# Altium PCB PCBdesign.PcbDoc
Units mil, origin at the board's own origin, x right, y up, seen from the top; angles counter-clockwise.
Board outline 6000 x 4000 mil, 2 copper layers (Top Layer, Bottom Layer); 43 components, 39 nets, 166 pads, 16 vias.
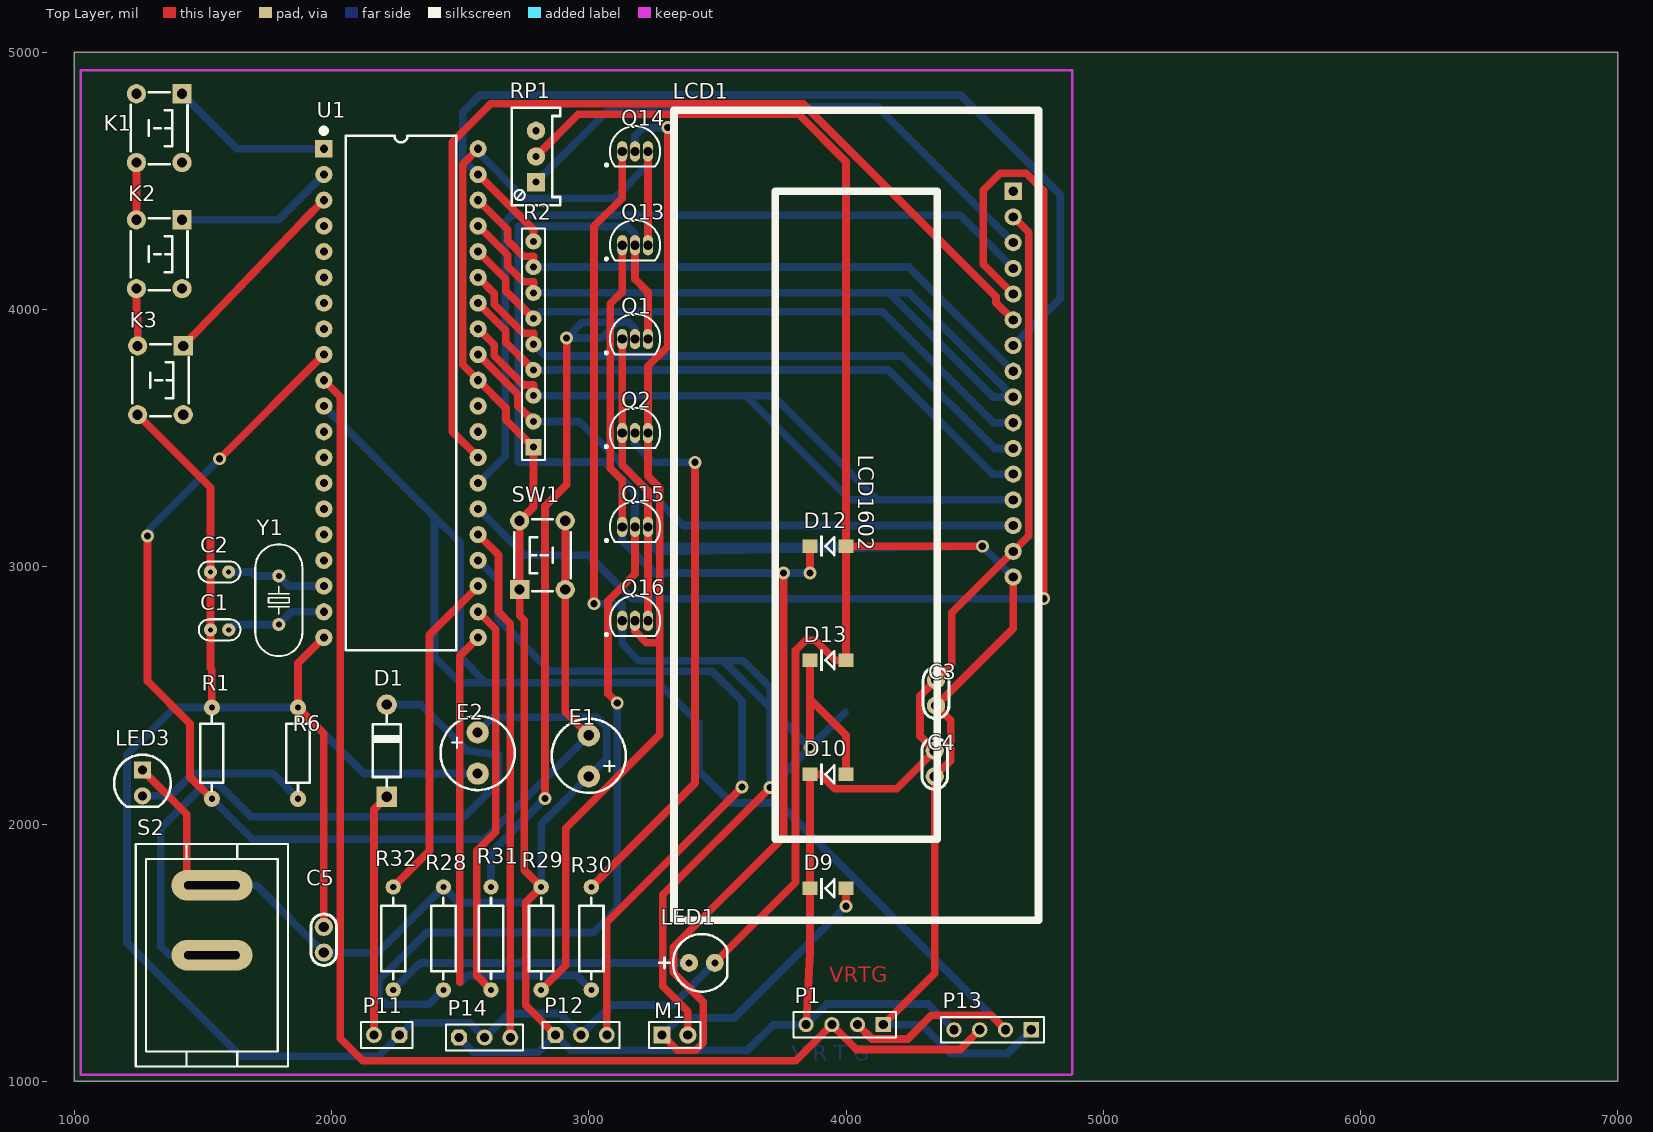
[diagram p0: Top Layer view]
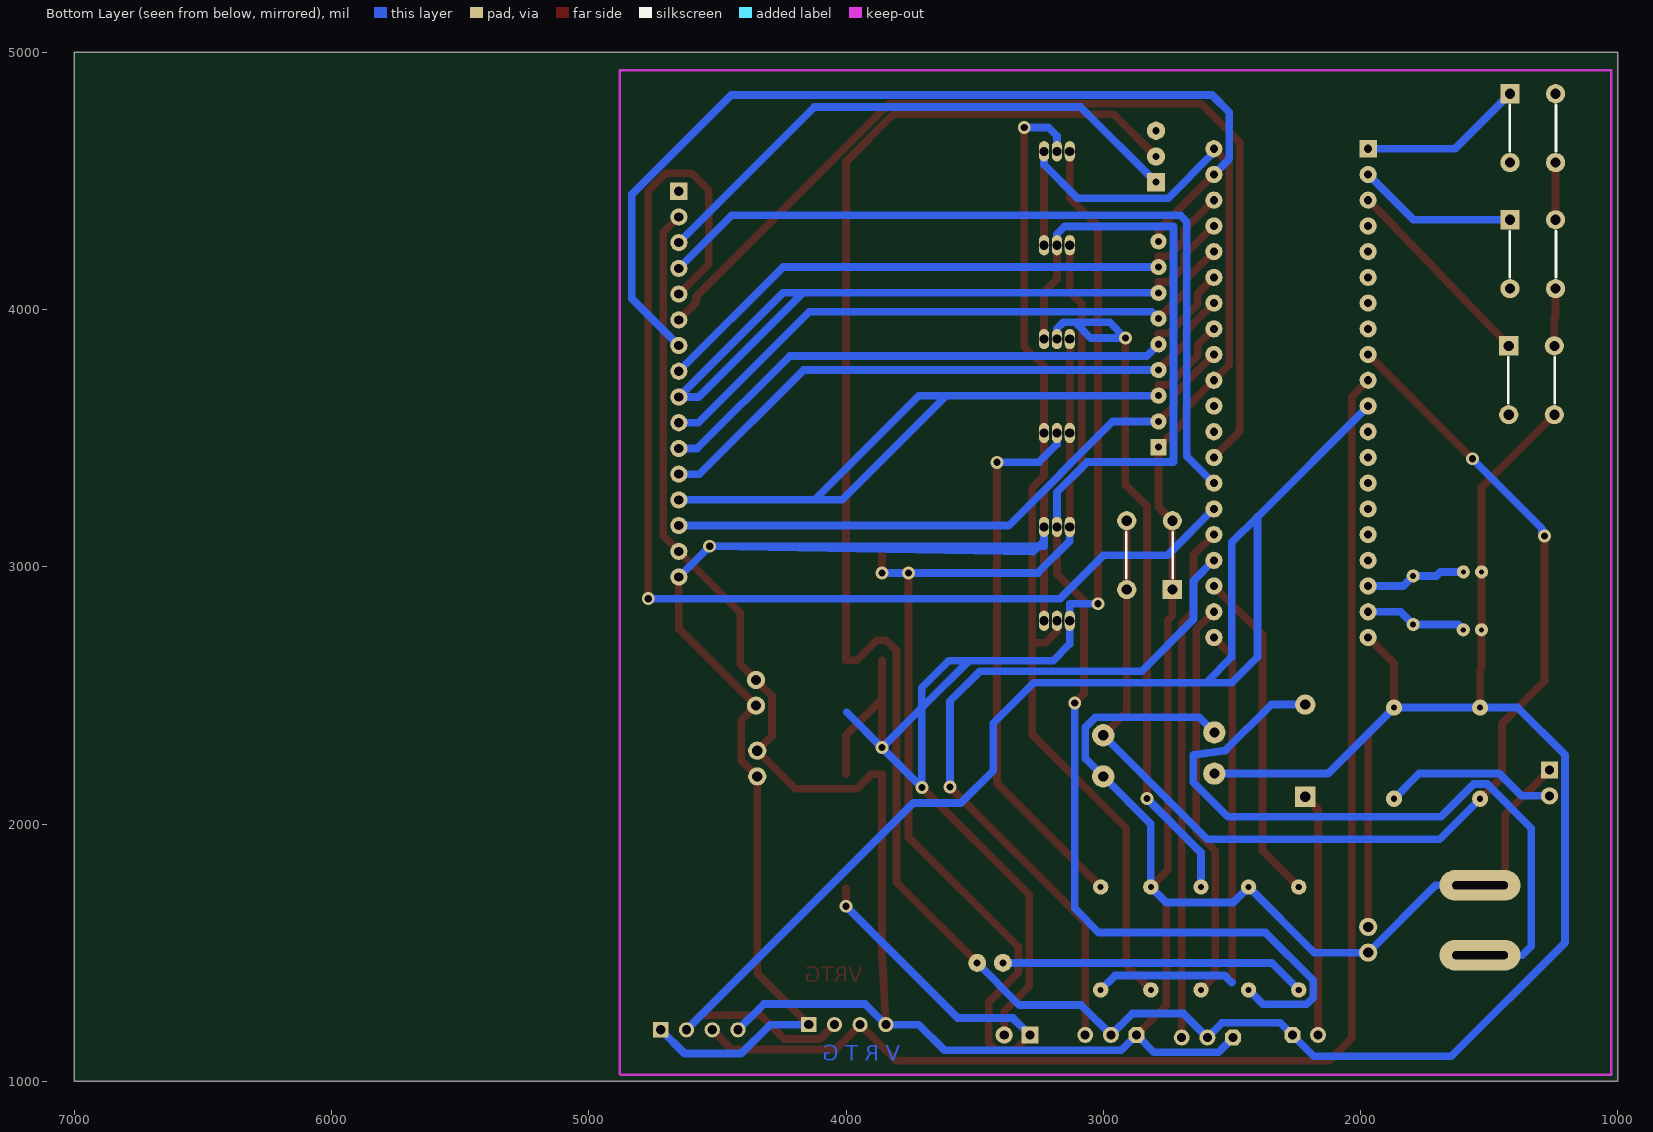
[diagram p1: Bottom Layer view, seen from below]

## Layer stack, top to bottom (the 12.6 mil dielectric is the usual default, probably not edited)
Top Solder: solder mask 0.4, Solder Resist, Dk 3.5
Top Layer: signal copper 1.4
Dielectric 1: dielectric 12.6, FR-4, Dk 4.8
Bottom Layer: signal copper 1.4
Bottom Solder: solder mask 0.4, Solder Resist, Dk 3.5

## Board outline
1000,1000 7000,1000 7000,5000 1000,5000

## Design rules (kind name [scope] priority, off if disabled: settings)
Clearance [All] p1: gap=11 ignorepadtopadclearanceinfootprint=TRUE
ComponentClearance [All] p1: gap=0 collisioncheckmode=3 verticalgap=0 showdistances=TRUE
PolygonConnect [All] p1: connectstyle=Relief reliefconductorwidth=10 reliefentries=4 polygonreliefangle="90 Angle" airgapwidth=10
RoutingVias [All] p1: holewidth=28 width=50 viastyle="Through Hole" minholewidth=28 minwidth=50 maxholewidth=28 maxwidth=50
SolderMaskExpansion [All] p1: expansion=4
Width [All] p1: maxlimit=35 minlimit=20 preferedwidth=30
29 further rules are at their usual default settings.

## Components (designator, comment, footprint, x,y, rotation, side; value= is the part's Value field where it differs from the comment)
C1 "33P" "CC 1.8*3.6" 1565,2755 r180 top
C2 "33P" "CC 1.8*3.6" 1564.57,2980 r180 top
C3 "100pF" RAD0.1 4350,2460 r90 top
C4 "104" RAD0.1 4345,2185 r90 top
C5 "104" RAD0.1 1970,1500 r90 top
D1 "N4007" DO-41 2214.62,2285.16 r90 top
D9 "IN4148" DIODE_SOP 3930,1750 r180 top
D10 "IN4148" DIODE_SOP 3930,2193.33 r180 top
D12 "IN4148" DIODE_SOP 3930,3080 r180 top
D13 "IN4148" DIODE_SOP 3930,2636.67 r180 top
E1 "10uF/16V" CAP_2 3003,2266 r270 top
E2 "470" CAP_2 2565,2275 r90 top
K1 "6x6x5" "TSW DIP-6*6*6" 1330,4705 r270 top
K2 "6x6x5" "TSW DIP-6*6*6" 1330,4215 r270 top
K3 "6x6x5" "TSW DIP-6*6*6" 1335,3725 r270 top
LCD1 "LCD 1602" LCD-1602 4650,4460 r270 top
LED1 "LED" LED-D5 3440,1460 r0 top
LED3 "蓝色" "LED 5MM-G" 1265,2159.38 r270 top
M1 "HDR-1X2" HDR2.54-LI-2P 3335,1180 r0 top
P1 "HC-05" HDR1X4 4145,1220 r180 top
P11 "POWER" COM2-2.54 2215,1180 r180 top
P12 "COM3-2.54" COM3-2.54 2970,1180 r0 top
P13 "XZ" HDR1X4 4720,1200 r180 top
P14 "COM3-2.54" COM3-2.54 2595,1170 r0 top
Q1 "S8050" TO-92 3180,3885 r0 top
Q2 "S8050" TO-92 3180,3520 r0 top
Q13 "S8050" TO-92 3180,4250 r0 top
Q14 "S8050" TO-92 3180,4615 r0 top
Q15 "S8550" TO-92 3180,3155 r0 top
Q16 "S8550" TO-92 3180,2790 r0 top
R1 "1K" "RS 1/4W" 1534.71,2275.32 r90 top
R2 "103" "R SIP9-2.54" 2785,3865 r90 top
R6 "1K" "RS 1/4W" 1869.67,2275.32 r270 top
R28 "1K" RES-0.25W-6.5X2.5-10.16-0.6 2435,1555 r90 top
R29 "1K" RES-0.25W-6.5X2.5-10.16-0.6 2815,1555 r90 top
R30 "1K" RES-0.25W-6.5X2.5-10.16-0.6 3010,1555 r90 top
R31 "1K" RES-0.25W-6.5X2.5-10.16-0.6 2620,1555 r90 top
R32 "1K" RES-0.25W-6.5X2.5-10.16-0.6 2240,1555 r90 top
RP1 "10K" 3296W 2795,4595 r90 top
S2 "POWER" KCD1-101 1535,1490 r90 top
SW1 "6x6x5" "TSW DIP-6*6*6" 2820,3045 r90 top
U1 "STC89C5xx" DIP40-600 2270,3675 r0 top
Y1 "11.0592MHz" "OSC HC-49S" 1795,2870 r90 top

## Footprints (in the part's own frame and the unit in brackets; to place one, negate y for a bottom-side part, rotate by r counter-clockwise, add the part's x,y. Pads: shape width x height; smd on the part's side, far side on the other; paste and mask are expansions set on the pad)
3296W [mm] "Precise Multi-Winding Adjustable Resistor"
  rect 1.8x1.8 hole 0.7: 1(-2.54,0)
  round 1.8 hole 0.7: 2(0,0) 3(2.54,0)
  silkscreen extent -4.8,-2.4 4.8,2.4, body extent -4.75,-2.4 4.75,2.4, height 11.52
CAP_2 [mm]
  round 2.2 hole 1: 1(2.057,-0.076) 2(-2.007,-0.076)
  silkscreen extent -3.64,-3.74 3.69,3.59, body extent -4.03,-4.08 4.03,3.97, height 12.03
"CC 1.8*3.6" [mm] "脚距1.8mm直径3.6mm"
  round 1.3 hole 0.5: 1(-0.9,0) 2(0.9,0)
  silkscreen extent -2.05,-1.04 2.05,1.04, body extent -1.8,-0.8 1.8,0.8, height 3.6
COM2-2.54 [mil] "Connector; Header; 2 Position"
  oct 62x62 hole 35: 1(-50,0)
  round 62 hole 35: 2(50,0)
  silkscreen extent -100,-50 100,50, body extent -100,-50 100,50, height 336
COM3-2.54 [mil]
  oct 62x62 hole 35: 1(-100,0)
  round 62 hole 35: 2(0,0) 3(100,0)
  silkscreen extent -150,-50 150,50, body extent -151,-50 149,50, height 398
DIODE_SOP [mm]
  rect 1.5x1.3 smd: 1(-1.778,0) 2(1.778,0)
  silkscreen extent -0.64,-1.02 0.78,1.02, body extent -1.93,-0.72 1.57,0.78, height 1.51
DIP40-600 [mm] "52*15.2*4mm(长宽高)"
  rect 1.7x1.7 hole 0.8: 1(-7.62,24.13)
  round 1.7 hole 0.8: 2(-7.62,21.59) 3(-7.62,19.05) 4(-7.62,16.51) 5(-7.62,13.97) 6(-7.62,11.43) 7(-7.62,8.89) 8(-7.62,6.35) 9(-7.62,3.81) 10(-7.62,1.27) 11(-7.62,-1.27) 12(-7.62,-3.81) 13(-7.62,-6.35) 14(-7.62,-8.89) 15(-7.62,-11.43) 16(-7.62,-13.97) 17(-7.62,-16.51) 18(-7.62,-19.05) 19(-7.62,-21.59) 20(-7.62,-24.13) 21(7.62,-24.13) 22(7.62,-21.59) 23(7.62,-19.05) 24(7.62,-16.51) 25(7.62,-13.97) 26(7.62,-11.43) 27(7.62,-8.89) 28(7.62,-6.35) 29(7.62,-3.81) 30(7.62,-1.27) 31(7.62,1.27) 32(7.62,3.81) 33(7.62,6.35) 34(7.62,8.89) 35(7.62,11.43) 36(7.62,13.97) 37(7.62,16.51) 38(7.62,19.05) 39(7.62,21.59) 40(7.62,24.13)
  silkscreen extent -7.87,-25.4 5.46,26.16, body extent -7.78,-26.18 7.78,26.18, height 4.7
DO-41 [mm] "2.6*9.1mm(直径，脚距）"
  rect 2x2 hole 1: 1(-4.55,0)
  round 2 hole 1: 2(4.55,0)
  silkscreen extent -3.56,-1.4 3.56,1.4, body extent -4.92,-1.29 4.98,1.31, height 2.65
HDR1X4 [mm] "Connector; Header; 4 Position"
  rect 1.5x1.5 hole 0.9: 1(0,0)
  round 1.5 hole 0.9: 2(2.54,0) 3(5.08,0) 4(7.62,0)
  silkscreen extent -1.27,-1.27 8.89,1.27
HDR2.54-LI-2P [mm]
  rect 1.7x1.7 hole 0.9: 1(-1.27,0)
  round 1.7 hole 0.9: 2(1.27,0)
  silkscreen extent -2.54,-1.27 2.54,1.27, body extent -2.54,-1.27 2.54,1.27, height 8.5
KCD1-101 [mm] "船型开关立式"
  oval 3x8 hole 0.8 slot 5.5 at 90 deg: 1(0,0) 2(6.9,0)
  silkscreen extent -10.97,-7.52 10.97,7.52, body extent -10.95,-7.5 10.95,7.5, height 20.3
LCD-1602 [mm] "LCD module 16*2 char"
  rect 1.7x1.7 hole 0.9: 1(0,0)
  round 1.7 hole 0.9: 2(2.54,0) 3(5.08,0) 4(7.62,0) 5(10.16,0) 6(12.7,0) 7(15.24,0) 8(17.78,0) 9(20.32,0) 10(22.86,0) 11(25.4,0) 12(27.94,0) 13(30.48,0) 14(33.02,0) 15(35.56,0) 16(38.1,0)
  silkscreen extent -8,-33.5 72,2.5, body extent -8.15,-33.11 71.85,1.89, height 9
"LED 5MM-G" [mm] "绿色5mm直插LED"
  rect 1.7x1.7 hole 0.9: 1(-1.27,0)
  round 1.7 hole 0.9: 2(1.27,0)
  silkscreen extent -2.8,-2.8 2.33,2.8, body extent -2.85,-2.85 2.45,2.85, height 8.75
LED-D5 [mil] "LED"
  round 70 hole 27.56: 1(-50,0) 2(50,0)
  silkscreen extent -165,-112 98,112, body extent -108,-118 105,119, height 485
"OSC HC-49S" [mm]
  round 1.3 hole 0.6: 1(-2.4,0) 2(2.4,0)
  silkscreen extent -5.52,-2.32 5.52,2.33, body extent -5.52,-2.32 5.53,2.33, height 4.13
"R SIP9-2.54" [mm] "22.6mm*5mm*2.2mm(长*宽*厚)"
  rect 1.6x1.6 hole 0.7: 1(-10.16,0)
  round 1.6 hole 0.7: 2(-7.62,0) 3(-5.08,0) 4(-2.54,0) 5(0,0) 6(2.54,0) 7(5.08,0) 8(7.62,0) 9(10.16,0)
  silkscreen extent -11.43,-1.14 11.43,1.14, body extent -11.31,-0.96 11.31,0.96, height 5.2
RAD0.1 [mm]
  round 1.8 hole 1: 1(0,0) 2(2.54,0)
  silkscreen extent -1.27,-1.27 3.81,1.27
RES-0.25W-6.5X2.5-10.16-0.6 [mil] "Resistor, 0.25W"
  round 60 hole 23.62: 1(-200,0) 2(200,0)
  silkscreen extent -157,-47 157,47, body extent -212,-45 212,46, height 92
"RS 1/4W" [mm] "直插色环电阻，脚距9mm，直径2.3mm"
  round 1.6 hole 0.6: 1(-4.5,0) 2(4.5,0)
  silkscreen extent -3.68,-1.14 3.68,1.14, body extent -4.72,-1.16 4.73,1.16, height 2.32
TO-92 [mm]
  oval 1x2 hole 0.9: 1(-1.27,0) 2(0,0) 3(1.27,0)
  silkscreen extent -2.95,-1.5 2.48,2.48, body extent -2.45,-1.68 2.35,2.32, height 8.09
"TSW DIP-6*6*6" [mm] "6*6*6mm"
  rect 1.9x1.9 hole 1: 1(-3.4,2.25)
  round 1.9 hole 1: 2(-3.4,-2.25) 3(3.4,-2.25) 4(3.4,2.25)
  silkscreen extent -3.56,-2.79 3.56,2.79, body extent -4.11,-3 4.11,3, height 5.95

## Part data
C1 C2: library part C-CC, "直插瓷片电容"
C3 C4 C5: library part 普通电容, "Capacitor"
D1: library part 1N4007, "整流二极管"
E1 E2: library part 电解电容, "Capacitor"
K1 K2 K3 SW1: library part "TSW DIP-6x6", "直插6x6轻触开关"
LED3: library part LED-5MM, "5mm插件LED"
M1: library part "Header 2", "2P接插件"
P1 P13: library part "Header 4", "Header, 4-Pin"
P11: library part COM2-2.54
Q1 Q2 Q13 Q14: "NPN", Manufacturer #2=8050
Q15 Q16: "PNP"
R1 R6: library part R-CRR, "直插色环电阻"
R2: library part "R SIP9", "单列直插排阻"
R28 R29 R30 R31 R32: library part RES, "Resistor"
RP1: library part RP-ID, "插件单联电位器"
S2: library part KCD1-101, "1路单刀船型开关"
U1: "STC单片机"
Y1: library part XTAL-2P, "2脚无源脚晶振"

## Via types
v1: diameter 50, hole 28, Top Layer to Bottom Layer, 16 vias

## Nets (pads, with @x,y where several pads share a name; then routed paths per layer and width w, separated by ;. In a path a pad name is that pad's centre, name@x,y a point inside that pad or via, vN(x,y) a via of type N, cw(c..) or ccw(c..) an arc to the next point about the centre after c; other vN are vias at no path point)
GND: C1.2 C2.2 C3.1 C4.1 C5.2 D12.1 D13.1 E2.2 K3.3 LCD1.16 LED1.2 P1.1 P11.1 P12.2 P13.1 P14.2 Q1.1 Q2.1 Q15.3 Q16.3 R1.2 R6.1 RP1.2 U1.20 | length 19537.2
  Top Layer w30: K3.3 1529.13,3308.43 C2.2 1529.13,2867.43 1529.57,2867 C1.2 1529.57,2606.15 1534.71,2601 R1.2 ; C5.2 1970,2352.15 R6.1 1869.67,2624.67 U1.20 ; RP1.2 2959,4759 3816,4759 4000,4575 D12.1 ; Q1.1 Q2.1 3130,3395 3230,3295 Q15.3 Q16.3 ; LED1.2 3804,1774 3804,2675 3843,2714 3880.67,2714 3958,2636.67 D13.1 D12.1 ; P1.1 4345,1420 C4.1 4407,2247 4407,2403 C3.1 4650,2760 LCD1.16 ; v1(4530,3080) D12.1
  Bottom Layer w30: E2.2 2126.15,2196 R6.1 R1.2 1388.48,2452.48 1205,2269 1205,1539 1647,1097 2182,1097 P11.1 2312,1227 2538,1227 P14.2 2688,1263 2887,1263 P12.2 3086,1296 3326,1296 LED1.2 ; Q15.3 3230,3100 ; P1.1 4295,1220 4407,1108 4628,1108 P13.1 ; LCD1.16 v1(4530,3080) ; 3230,3100 3250,3080 ; 3230,3100 3230,3080 3250,3080 ; 3250,3080 v1(4530,3080) ; 3250,3080 3272,3058 v1(4530,3080)
NetD1_1: D1.1 P11.2 | length 946.6
  Top Layer w30: P11.2 2165,2056.41 D1.1
NetD1_2: D1.2 S2.1 | length 2782.5
  Bottom Layer w30: S2.1 1371,1490 1336,1525 1336,1984 1507.65,2155.65 1559.35,2155.65 1687,2028 2516,2028 2650,2162 2650,2268 2525,2286 2346.71,2464.29 D1.2
NetD9_1: D9.1 D12.2 M1.1 Q13.1 Q15.1 | length 5313.7
  Top Layer w30: Q15.1 3130,3337 3084,3383 3084,4022 3130,4068 Q13.1 ; M1.1 3344.47,1120.53 3415.53,1120.53 3445,1150 3445,1308 3329,1424 3329,1521 3757,1949 v1(3757,2976) ; v1(3860,2976) D12.2 ; v1(4000,1680) D9.1
  Bottom Layer w30: Q15.1 3130,3100 3254,2976 v1(3757,2976) v1(3860,2976) ; M1.1 3351,1246 3566,1246 v1(4000,1680)
NetD10_1: D10.1 D13.2 M1.2 Q14.1 Q16.1 | length 5859.9
  Top Layer w30: v1(3020,2856) 3020,4323 3130,4433 Q14.1 ; M1.2 3385,1272 3288,1369 3288,1725 v1(3705,2142) ; v1(3860,2297) 3860,2485 ; D13.2 3860,2485 ; D10.1 4000,2345 3860,2485
  Bottom Layer w30: v1(3020,2856) 3130,2856 Q16.1 3130,2700 3195,2635 3522,2635 ; 3997.5,2434.5 v1(3860,2297) ; 3522,2635 3705,2452 ; 3522,2635 3600,2635 3705,2530 3705,2452 ; 3705,2452 v1(3860,2297) ; 3705,2452 v1(3705,2142) v1(3860,2297)
NetK1_3: K1.3 K2.2 | length 222.3
  Top Layer w30: K2.2 K1.3
NetK2_3: K2.3 K3.2 | length 224.4
  Top Layer w30: K2.3 1241.42,3972 1246.42,3967 K3.2
NetLCD1_3: LCD1.3 RP1.1 | length 2194.2
  Bottom Layer w30: RP1.1 3087,4787 4123,4787 LCD1.3
NetLED1_1: LED1.1 R32.1 | length 1193.5
  Bottom Layer w30: R32.1 2345,1460 LED1.1
NetLED3_2: LED3.2 R6.2 | length 681.6
  Bottom Layer w30: LED3.2 1374,2109.38 1461.27,2196.65 1771.17,2196.65 R6.2
NetQ1_1: Q1.2 R31.2 | length 2818.5
  Top Layer w30: v1(2830,2099) 2830,3236 2914,3320 v1(2914,3889)
  Bottom Layer w30: R31.2 2620,1889 v1(2830,2099) ; Q1.2 3180,3925 3154.63,3950.37 3109.37,3950.37 ; 3109.37,3950.37 2975.37,3950.37 v1(2914,3889) 3048,3889 3109.37,3950.37
NetQ1_3: Q1.3 Q13.2 Q15.2 R28.1 | length 5383.5
  Top Layer w30: v1(3111,2470) 3075,2506 3075,2868 3180,2973 Q15.2 ; Q13.2 3180,4118 3230,4068 Q1.3
  Bottom Layer w30: R28.1 2379,1299 2210,1299 2184,1325 2184,1393 2369,1578 3017,1578 3111,1672 v1(3111,2470) ; Q15.2 3180,3290 3063,3407 2727,3407 2727,4323 3150,4323 3180,4293 Q13.2
NetQ2_1: Q2.2 R30.2 | length 2123.9
  Top Layer w30: R30.2 3413,2158 v1(3413,3406)
  Bottom Layer w30: Q2.2 3180,3476 3250,3406 v1(3413,3406)
NetQ2_3: Q2.3 Q14.2 Q16.2 R29.1 | length 3950.8
  Top Layer w30: R29.1 2911,1451 2911,1983 3276,2348 3276,2705 ; Q16.2 3180,2749 3224,2705 3276,2705 ; v1(3307,4708) 3307,3856 3230,3779 Q2.3 3230,3353 3276,3307 3276,2705
  Bottom Layer w30: Q14.2 3180,4675 3213,4708 v1(3307,4708)
P00: LCD1.7 R2.9 U1.39 | length 3789.8
  Top Layer w30: U1.39 2785,4310 R2.9
  Bottom Layer w30: U1.39 2510,4585 2510,4767 2577,4834 4446,4834 4833,4447 4833,4043 LCD1.7
P01: LCD1.8 R2.8 U1.38 | length 2404.7
  Top Layer w30: U1.38 2684.53,4310.47 2684.53,4268.45 2745.98,4207 2785,4207 R2.8
  Bottom Layer w30: R2.8 4245,4165 LCD1.8
P02: LCD1.9 R2.7 U1.37 | length 3055.7
  Top Layer w30: U1.37 2684.53,4210.47 2684.53,4168.45 2745.48,4107.5 2785,4107.5 R2.7
  Bottom Layer w30: R2.7 4167.01,4065 ; 4167.01,4065 4245,4065 LCD1.9 4572.01,3660 4167.01,4065
P03: LCD1.10 R2.6 U1.36 | length 2403.7
  Top Layer w30: U1.36 2677.82,4117.18 2677.82,4072.18 R2.6
  Bottom Layer w30: R2.6 2811.37,3991.37 4142.76,3991.37 4574.13,3560 LCD1.10
P04: LCD1.11 R2.5 U1.35 | length 2405
  Top Layer w30: U1.35 2632.67,4062.33 2632.67,4020.31 2745.48,3907.5 2785,3907.5 R2.5
  Bottom Layer w30: R2.5 2831,3819 4219.06,3819 4578.06,3460 LCD1.11
P05: LCD1.12 R2.4 U1.34 | length 2381.8
  Top Layer w30: U1.34 2677.82,3917.18 2677.82,3872.18 R2.4
  Bottom Layer w30: R2.4 4165,3765 4570,3360 LCD1.12
P06: LCD1.13 R2.3 U1.33 | length 3084.4
  Top Layer w30: U1.33 2632.67,3862.33 2632.67,3820.31 2745.98,3707 2785,3707 R2.3
  Bottom Layer w30: R2.3 3610,3665 ; LCD1.13 4122,3260 ; 3610,3665 3717,3665 4122,3260 ; 3610,3665 4015,3260 4122,3260
P07: LCD1.14 R2.2 U1.32 | length 2381.8
  Top Layer w30: U1.32 2724,3671 2724,3626 R2.2
  Bottom Layer w30: R2.2 2963,3565 3368,3160 LCD1.14
P10: K1.1 U1.1 | length 640
  Bottom Layer w30: K1.1 1632.44,4625 U1.1
P11: K2.1 U1.2 | length 624.4
  Bottom Layer w30: K2.1 1793.86,4348.86 U1.2
P12: K3.1 U1.3 | length 786.8
  Top Layer w30: K3.1 1889,4344 U1.3
P20: R30.1 U1.21 | length 1917.4
  Top Layer w30: 2498,1385 2498,2653 U1.21
  Bottom Layer w30: 2498,1385 2500,1383 2528,1411 2954,1411 R30.1
P21: R31.1 U1.22 | length 1552
  Top Layer w30: U1.22 2638,2757 2638,1970 2564,1896 2564,1411 R31.1
P22: R32.2 U1.23 | length 1306.7
  Top Layer w30: R32.2 2381,1896 2381,2736 U1.23
P23: P12.3 U1.24 | length 2855.7
  Top Layer w30: P12.3 3070,1618 v1(3596,2144)
  Bottom Layer w30: U1.24 2649,2946 2649,2796 2851,2594 3479,2594 3596,2477 v1(3596,2144)
P24: P14.3 U1.25 | length 2006.8
  Top Layer w30: U1.25 2649,3046 2649,2825 2695,2779 P14.3
P25: LCD1.5 U1.26 | length 4671.5
  Top Layer w30: LCD1.5 4534,4176 4534,4464 4600,4530 4700,4530 4769,4461 v1(4769,2876)
  Bottom Layer w30: U1.26 2750,3045 2999,3045 3168,2876 v1(4769,2876)
P26: LCD1.4 U1.27 | length 3130.2
  Bottom Layer w30: U1.27 2675,3430 2675,4341 2700,4366 4444,4366 LCD1.4
P27: LCD1.6 U1.28 | length 3871.4
  Top Layer w30: U1.28 2469,3526 2469,4650 2619,4800 3833,4800 4583,4050 4583,4027 LCD1.6
RES: E1.2 R1.1 SW1.2 SW1.3 U1.9 | length 4693.5
  Top Layer w30: v1(1285,3120) 1285,2565 1285,2555 1450,2390 1450,2182.86 R1.1 ; v1(1565,3420) U1.9 ; SW1.3 SW1.2 2908.58,2436.42 E1.2
  Bottom Layer w30: v1(1285,3120) 1285,3125 1280,3130 1285,3135 1295,3135 1295,3150 v1(1565,3420) ; R1.1 1691.86,1941 2596,1941 E1.2
RXD: P1.3 P13.3 U1.10 | length 5237
  Top Layer w30: U1.10 2034,3661 2034,1167 2121.47,1079.53 3804.53,1079.53 P1.3 4042,1123 4443,1123 P13.3
TXD: P1.2 P13.2 U1.11 | length 5470.1
  Top Layer w30: P1.2 4101,1164 4240,1164 4332,1256 4564,1256 P13.2
  Bottom Layer w30: U1.11 2400,3195 ; P13.2 3738.47,2081.53 3553.56,2081.53 3428.03,2207.06 3428.03,2391.97 3270.45,2549.55 2600,2549.55 ; 2400,3195 2500,3095 2500,2649.55 2600,2549.55 ; 2400,3195 2400,2649.55 2500,2549.55 2600,2549.55
VCC: C3.2 C4.2 C5.1 D9.2 D10.2 E1.1 E2.1 LCD1.2 LCD1.15 LED3.1 P1.4 P12.1 P13.4 P14.1 Q13.3 Q14.3 R2.1 R28.2 R29.2 S2.2 SW1.1 SW1.4 U1.31 U1.40 | length 14319.8
  Top Layer w30: LED3.1 1437,2037.38 1437,1761.65 S2.2 ; U1.40 2510,4565 2510,3785 U1.31 2678,3617 2678,3572 R2.1 2785,3232.44 SW1.4 SW1.1 2731.42,2809.58 2749,2792 2749,1821 R29.2 2755,1695 2755,1295 P12.1 ; Q13.3 Q14.3 ; P1.4 3860,1500 D9.2 D10.2 3901,2193.33 3957.33,2137 4197,2137 C4.2 4288,2342 4288,2498 C3.2 4410.87,2620.87 4410.87,2820.87 LCD1.15 4710,3120 4710,4300 LCD1.2
  Bottom Layer w30: S2.2 1708.35,1761.65 C5.1 2180,1500 R28.2 2495,1695 2755,1695 R29.2 2815,2000 E1.1 3070,2255 3070,2375 3030,2415 2627,2415 E2.1 ; P14.1 2552,1113 2803,1113 P12.1 2930,1120 3617,1120 3717,1220 P1.4 3925,1300 4320,1300 P13.4 ; U1.40 2570,4611 2748,4433 3100,4433 3230,4563 Q14.3
X1: C2.1 U1.18 Y1.2 | length 392.8
  Bottom Layer w30: C2.1 1689,2980 1704.51,2964.49 Y1.2 1834.49,2925 U1.18
X2: C1.1 U1.19 Y1.1 | length 398.6
  Bottom Layer w30: C1.1 1620.95,2775.51 Y1.1 1844.49,2825 U1.19
pads on no net: K1.2 K1.4 K2.4 K3.4 LCD1.1 RP1.3 U1.4 U1.5 U1.6 U1.7 U1.8 U1.12 U1.13 U1.14 U1.15 U1.16 U1.17 U1.29 U1.30

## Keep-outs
Keep-Out Layer:
  lines w10: 1025,1025 4875,1025 4880,1030 4880,4930 1025,4930 1025,1025

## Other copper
Top Layer:
  text "VRTG" at 3935,1385 h60
Bottom Layer:
  text "V R T G" at 3790,1080 h60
